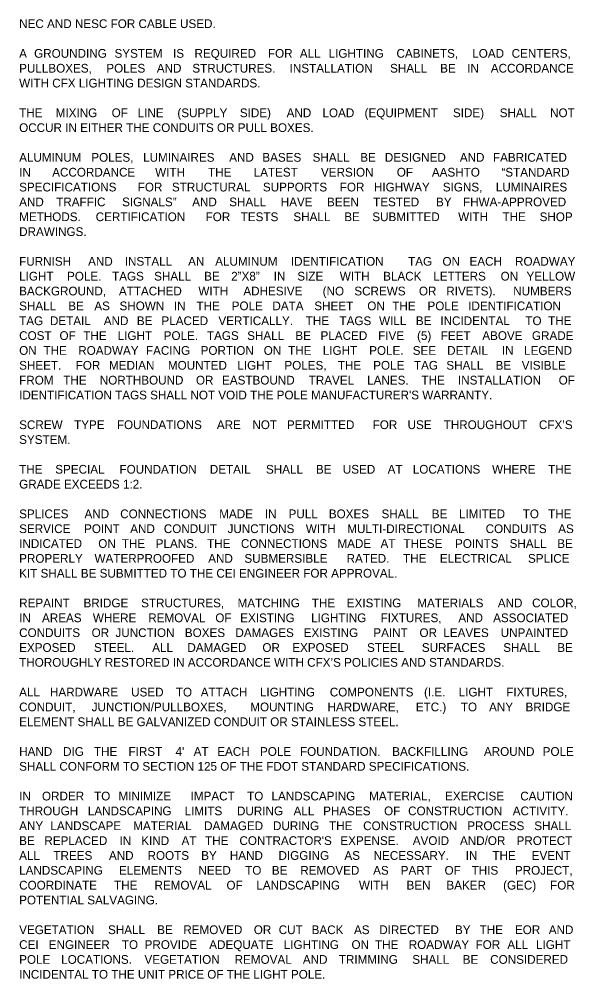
# Model space of a CAD drawing. Extents: x -55 to 2471539, y -90 to 3608906.
# Drawn here: x 568 to 1014, y 8 to 777 of the extents above; entities that cross this region are included whole.
import ezdxf

# ---------------------------------------------------------------- set-up
doc = ezdxf.new("R2010")
doc.units = 0
doc.layers.add('XSCell', color=7, linetype='Continuous')

msp = doc.modelspace()

# ---------------------------------------------------------------- texts
at = {"layer": 'XSCell'}
for s, p in [('NEC AND NESC FOR CABLE USED.', (568.01, 770.14)), ('GROUNDING ', (580.01, 746.34)), ('SYSTEM ', (644.47, 746.34)), ('IS ', (691.38, 746.34)), ('REQUIRED ', (708.58, 746.34)), ('FOR ', (767.49, 746.34)), ('LIGHTING ', (816.15, 746.34)), ('CABINETS, ', (870.55, 746.34)), ('LOAD ', (931.31, 746.34)), ('CENTERS, ', (962.92, 746.34)), ('A ', (568.01, 746.34)), ('ALL ', (793.05, 746.34)), ('PULLBOXES, ', (568.01, 734.44)), ('POLES ', (637.9, 734.44)), ('AND ', (678.37, 734.44)), ('STRUCTURES. ', (706.88, 734.44)), ('INSTALLATION ', (784.88, 734.44)), ('SHALL ', (865.42, 734.44)), ('BE ', (905.55, 734.44)), ('IN ', (927.24, 734.44)), ('ACCORDANCE ', (946.18, 734.44)), ('WITH CFX LIGHTING DESIGN STANDARDS.', (568.01, 722.54)), ('THE ', (568.01, 698.74)), ('MIXING ', (597.31, 698.74)), ('OF ', (642.19, 698.74)), ('LINE ', (663, 698.74)), ('(SUPPLY ', (694.88, 698.74)), ('SIDE) ', (744.95, 698.74)), ('AND ', (782.46, 698.74)), ('LOAD ', (811.22, 698.74)), ('(EQUIPMENT ', (844.96, 698.74)), ('SIDE) ', (915.82, 698.74)), ('SHALL ', (953.33, 698.74)), ('NOT ', (993.71, 698.74)), ('OCCUR IN EITHER THE CONDUITS OR PULL BOXES.', (568.01, 686.84)), ('ALUMINUM ', (568.01, 663.04)), ('POLES, ', (625.83, 663.04)), ('LUMINAIRES ', (667.41, 663.04)), ('AND ', (736.42, 663.04)), ('BASES ', (762.98, 663.04)), ('SHALL ', (803.29, 663.04)), ('BE ', (841.48, 663.04)), ('DESIGNED ', (861.21, 663.04)), ('AND ', (921.34, 663.04)), ('FABRICATED ', (947.9, 663.04)), ('IN ', (568.01, 651.14)), ('ACCORDANCE ', (594.51, 651.14)), ('WITH ', (677.06, 651.14)), ('THE ', (719.43, 651.14)), ('LATEST ', (756.05, 651.14)), ('VERSION ', (810.01, 651.14)), ('OF ', (870.8, 651.14)), ('AASHTO ', (898.93, 651.14)), ('“STANDARD ', (954.69, 651.14)), ('SPECIFICATIONS ', (568.01, 639.24)), ('FOR ', (663.12, 639.24)), ('STRUCTURAL ', (690.51, 639.24)), ('SUPPORTS ', (763.45, 639.24)), ('FOR ', (825.09, 639.24)), ('HIGHWAY ', (852.48, 639.24)), ('SIGNS, ', (907.69, 639.24)), ('LUMINAIRES ', (950.21, 639.24)), ('AND ', (568.01, 627.34)), ('TRAFFIC ', (597.7, 627.34)), ('SIGNALS” ', (650.56, 627.34)), ('AND ', (706.75, 627.34)), ('SHALL ', (736.44, 627.34)), ('HAVE ', (777.76, 627.34)), ('BEEN ', (814.87, 627.34)), ('TESTED ', (851.81, 627.34)), ('BY ', (902.26, 627.34)), ('FHWA-APPROVED ', (923.92, 627.34)), ('METHODS. ', (568.01, 615.44)), ('CERTIFICATION ', (629.39, 615.44)), ('FOR ', (717.5, 615.44)), ('TESTS ', (745.65, 615.44)), ('SHALL ', (787.89, 615.44)), ('BE ', (828.73, 615.44)), ('SUBMITTED ', (851.14, 615.44)), ('WITH ', (920.02, 615.44)), ('THE ', (955.54, 615.44)), ('SHOP ', (985.31, 615.44)), ('DRAWINGS.', (568.01, 603.54)), ('FURNISH ', (568.01, 579.74)), ('AND ', (623.29, 579.74)), ('INSTALL ', (652.69, 579.74)), ('AN ', (703.49, 579.74)), ('ALUMINUM ', (725.21, 579.74)), ('IDENTIFICATION ', (785.87, 579.74)), ('TAG ', (879.86, 579.74)), ('ON ', (907.43, 579.74)), ('EACH ', (929.1, 579.74)), ('ROADWAY ', (965.64, 579.74)), ('LIGHT ', (568.01, 567.84)), ('POLE. ', (606.39, 567.84)), ('TAGS ', (642.51, 567.84)), ('SHALL ', (676.24, 567.84)), ('BE ', (716.34, 567.84)), ('2”X8” ', (738.01, 567.84)), ('IN ', (772.11, 567.84)), ('SIZE ', (791.03, 567.84)), ('WITH ', (825.09, 567.84)), ('BLACK ', (859.87, 567.84)), ('LETTERS ', (900.07, 567.84)), ('ON ', (954.05, 567.84)), ('YELLOW ', (974.8, 567.84)), ('BACKGROUND, ', (568.01, 555.94)), ('ATTACHED ', (647.98, 555.94)), ('WITH ', (711.72, 555.94)), ('ADHESIVE ', (747.77, 555.94)), ('(NO ', (811.36, 555.94)), ('SCREWS ', (836.74, 555.94)), ('OR ', (888.54, 555.94)), ('RIVETS). ', (910.5, 555.94)), ('NUMBERS ', (964.15, 555.94)), ('SHALL ', (568.01, 544.04)), ('BE ', (607.37, 544.04)), ('AS ', (628.28, 544.04)), ('SHOWN ', (648.48, 544.04)), ('IN ', (691.99, 544.04)), ('THE ', (710.16, 544.04)), ('POLE ', (738.44, 544.04)), ('DATA ', (771.06, 544.04)), ('SHEET ', (804.66, 544.04)), ('ON ', (847.15, 544.04)), ('THE ', (867.16, 544.04)), ('POLE ', (895.44, 544.04)), ('IDENTIFICATION ', (928.06, 544.04)), ('TAG ', (568.01, 532.14)), ('DETAIL ', (592.69, 532.14)), ('AND ', (635.86, 532.14)), ('BE ', (662.38, 532.14)), ('PLACED ', (682.08, 532.14)), ('VERTICALLY. ', (727.77, 532.14)), ('THE ', (797.76, 532.14)), ('TAGS ', (824.83, 532.14)), ('WILL ', (856.59, 532.14)), ('BE ', (886.05, 532.14)), ('INCIDENTAL ', (905.75, 532.14)), ('TO ', (973.89, 532.14)), ('THE ', (992.12, 532.14)), ('COST ', (568.01, 520.24)), ('OF ', (600.37, 520.24)), ('THE ', (619.44, 520.24)), ('LIGHT ', (647, 520.24)), ('POLE. ', (683.91, 520.24)), ('TAGS ', (718.57, 520.24)), ('SHALL ', (750.83, 520.24)), ('BE ', (789.47, 520.24)), ('PLACED ', (809.66, 520.24)), ('FIVE ', (855.85, 520.24)), ('(5) ', (887.05, 520.24)), ('FEET ', (906.02, 520.24)), ('ABOVE ', (939.36, 520.24)), ('GRADE ', (979.17, 520.24)), ('ON ', (568.01, 508.34)), ('THE ', (587.57, 508.34)), ('ROADWAY ', (615.39, 508.34)), ('FACING ', (669.69, 508.34)), ('PORTION ', (713.51, 508.34)), ('ON ', (764.09, 508.34)), ('THE ', (783.65, 508.34)), ('LIGHT ', (811.48, 508.34)), ('POLE. ', (848.66, 508.34)), ('SEE ', (883.58, 508.34)), ('DETAIL ', (911.18, 508.34)), ('IN ', (955.12, 508.34)), ('LEGEND ', (972.84, 508.34)), ('SHEET. ', (568.01, 496.44)), ('FOR ', (613.33, 496.44)), ('MEDIAN ', (640.07, 496.44)), ('MOUNTED ', (687.27, 496.44)), ('LIGHT ', (742.99, 496.44)), ('POLES, ', (780.69, 496.44)), ('THE ', (823.52, 496.44)), ('POLE ', (851.88, 496.44)), ('TAG ', (884.57, 496.44)), ('SHALL ', (910.54, 496.44)), ('BE ', (949.98, 496.44)), ('VISIBLE ', (970.96, 496.44)), ('FROM ', (568.01, 484.54)), ('THE ', (603.39, 484.54)), ('NORTHBOUND ', (632.65, 484.54)), ('OR ', (709.75, 484.54)), ('EASTBOUND ', (730.69, 484.54)), ('TRAVEL ', (800.16, 484.54)), ('LANES. ', (847.03, 484.54)), ('THE ', (890.59, 484.54)), ('INSTALLATION ', (919.86, 484.54)), ('OF ', (1000.61, 484.54)), ("IDENTIFICATION TAGS SHALL NOT VOID THE POLE MANUFACTURER'S WARRANTY.", (568.01, 472.64)), ('SCREW ', (568.01, 448.84)), ('TYPE ', (612.05, 448.84)), ('FOUNDATIONS ', (646.38, 448.84)), ('ARE ', (726.54, 448.84)), ('NOT ', (755, 448.84)), ('PERMITTED ', (782.71, 448.84)), ('FOR ', (851.45, 448.84)), ('USE ', (879.44, 448.84)), ('THROUGHOUT ', (908.4, 448.84)), ('CFX’S ', (984.76, 448.84)), ('SYSTEM.', (568.01, 436.94)), ('THE ', (568.01, 413.14)), ('SPECIAL ', (596.95, 413.14)), ('FOUNDATION ', (648.45, 413.14)), ('DETAIL ', (720.86, 413.14)), ('SHALL ', (765.91, 413.14)), ('BE ', (805.93, 413.14)), ('USED ', (827.51, 413.14)), ('AT ', (863.48, 413.14)), ('LOCATIONS ', (883.63, 413.14)), ('WHERE ', (947.18, 413.14)), ('THE ', (992.12, 413.14)), ('GRADE EXCEEDS 1:2.', (568.01, 401.24)), ('SPLICES ', (568.01, 377.44)), ('AND ', (620.4, 377.44)), ('CONNECTIONS ', (649.03, 377.44)), ('MADE ', (728.42, 377.44)), ('IN ', (764.98, 377.44)), ('PULL ', (784.04, 377.44)), ('BOXES ', (816.31, 377.44)), ('SHALL ', (858.59, 377.44)), ('BE ', (898.84, 377.44)), ('LIMITED ', (920.65, 377.44)), ('TO ', (971.78, 377.44)), ('THE ', (992.12, 377.44)), ('SERVICE ', (568.01, 365.54)), ('POINT ', (620.07, 365.54)), ('AND ', (657.06, 365.54)), ('CONDUIT ', (684.01, 365.54)), ('JUNCTIONS ', (735.09, 365.54)), ('WITH ', (797.86, 365.54)), ('MULTI-DIRECTIONAL ', (831.11, 365.54)), ('CONDUITS ', (942.04, 365.54)), ('AS ', (1000.2, 365.54)), ('INDICATED ', (568.01, 353.64)), ('ON ', (631.45, 353.64)), ('THE ', (650.33, 353.64)), ('PLANS. ', (677.5, 353.64)), ('THE ', (718.68, 353.64)), ('CONNECTIONS ', (745.84, 353.64)), ('MADE ', (823.22, 353.64)), ('AT ', (857.76, 353.64)), ('THESE ', (876.13, 353.64)), ('POINTS ', (917.5, 353.64)), ('SHALL ', (961.24, 353.64)), ('BE ', (999.48, 353.64)), ('PROPERLY ', (568.01, 341.74)), ('WATERPROOFED ', (628.45, 341.74)), ('AND ', (719.6, 341.74)), ('SUBMERSIBLE ', (748.61, 341.74)), ('RATED. ', (830.55, 341.74)), ('THE ', (875.77, 341.74)), ('ELECTRICAL ', (905.32, 341.74)), ('SPLICE ', (975.98, 341.74)), ('KIT SHALL BE SUBMITTED TO THE CEI ENGINEER FOR APPROVAL.', (568.01, 329.84)), ('REPAINT ', (568.01, 306.04)), ('BRIDGE ', (619.62, 306.04)), ('STRUCTURES, ', (665.82, 306.04)), ('MATCHING ', (743.13, 306.04)), ('THE ', (802.64, 306.04)), ('EXISTING ', (830.7, 306.04)), ('MATERIALS ', (887.2, 306.04)), ('AND ', (951.78, 306.04)), ('COLOR, ', (979.3, 306.04)), ('IN ', (568.01, 294.14)), ('AREAS ', (586.33, 294.14)), ('WHERE ', (627.11, 294.14)), ('REMOVAL ', (671.54, 294.14)), ('OF ', (725.3, 294.14)), ('EXISTING ', (745.24, 294.14)), ('LIGHTING ', (802.12, 294.14)), ('FIXTURES, ', (857.79, 294.14)), ('AND ', (920.15, 294.14)), ('ASSOCIATED ', (948.05, 294.14)), ('CONDUITS ', (568.01, 282.24)), ('OR ', (626.11, 282.24)), ('JUNCTION ', (645.22, 282.24)), ('BOXES ', (700.86, 282.24)), ('DAMAGES ', (741.4, 282.24)), ('EXISTING ', (796.13, 282.24)), ('PAINT ', (852.01, 282.24)), ('OR ', (888.99, 282.24)), ('LEAVES ', (908.1, 282.24)), ('UNPAINTED ', (954.1, 282.24)), ('EXPOSED ', (568.01, 270.34)), ('STEEL. ', (627.98, 270.34)), ('ALL ', (674.69, 270.34)), ('DAMAGED ', (702.88, 270.34)), ('OR ', (763.04, 270.34)), ('EXPOSED ', (786.96, 270.34)), ('STEEL ', (846.94, 270.34)), ('SURFACES ', (890.89, 270.34)), ('SHALL ', (956.14, 270.34)), ('BE ', (999.48, 270.34)), ('THOROUGHLY RESTORED IN ACCORDANCE WITH CFX’S POLICIES AND STANDARDS. ', (568.01, 258.44)), ('ALL ', (568.01, 234.64)), ('HARDWARE ', (592.75, 234.64)), ('USED ', (657.8, 234.64)), ('TO ', (693.63, 234.64)), ('ATTACH ', (713.61, 234.64)), ('LIGHTING ', (761.04, 234.64)), ('COMPONENTS ', (817.08, 234.64)), ('(I.E. ', (892.66, 234.64)), ('LIGHT ', (920.42, 234.64)), ('FIXTURES, ', (958.58, 234.64)), ('CONDUIT, ', (568.01, 222.74)), ('JUNCTION/PULLBOXES, ', (626.15, 222.74)), ('MOUNTING ', (753.34, 222.74)), ('HARDWARE, ', (815.24, 222.74)), ('ETC.) ', (886.04, 222.74)), ('TO ', (922.13, 222.74)), ('ANY ', (944.79, 222.74)), ('BRIDGE ', (973.98, 222.74)), ('ELEMENT SHALL BE GALVANIZED CONDUIT OR STAINLESS STEEL.', (568.01, 210.84)), ('HAND ', (568.01, 187.04)), ('DIG ', (603.24, 187.04)), ('THE ', (627.99, 187.04)), ('FIRST ', (655.69, 187.04)), ("4' ", (693.4, 187.04)), ('AT ', (707.92, 187.04)), ('EACH ', (726.83, 187.04)), ('POLE ', (761.14, 187.04)), ('FOUNDATION. ', (793.18, 187.04)), ('BACKFILLING ', (867.11, 187.04)), ('AROUND ', (940.66, 187.04)), ('POLE ', (987.78, 187.04)), ('SHALL CONFORM TO SECTION 125 OF THE FDOT STANDARD SPECIFICATIONS.', (568.01, 175.14)), ('IN ', (568.01, 151.34)), ('ORDER ', (586.31, 151.34)), ('TO ', (628.08, 151.34)), ('MINIMIZE ', (647.66, 151.34)), ('IMPACT ', (705.48, 151.34)), ('TO ', (750.79, 151.34)), ('LANDSCAPING ', (770.36, 151.34)), ('MATERIAL, ', (848.58, 151.34)), ('EXERCISE ', (909.49, 151.34)), ('CAUTION ', (969.8, 151.34)), ('THROUGH ', (568.01, 139.44)), ('LANDSCAPING ', (623.09, 139.44)), ('LIMITS ', (700.68, 139.44)), ('DURING ', (742.68, 139.44)), ('ALL ', (788.03, 139.44)), ('PHASES ', (811.75, 139.44)), ('OF ', (860.6, 139.44)), ('CONSTRUCTION ', (879.89, 139.44)), ('ACTIVITY. ', (963.78, 139.44)), ('ANY ', (568.01, 127.54)), ('LANDSCAPE ', (593.07, 127.54)), ('MATERIAL ', (659.49, 127.54)), ('DAMAGED ', (716.29, 127.54)), ('DURING ', (771.54, 127.54)), ('THE ', (816.47, 127.54)), ('CONSTRUCTION ', (843.83, 127.54)), ('PROCESS ', (927.29, 127.54)), ('SHALL ', (981.03, 127.54)), ('BE ', (568.01, 115.64)), ('REPLACED ', (588.23, 115.64)), ('IN ', (648.46, 115.64)), ('KIND ', (665.93, 115.64)), ('AT ', (698.24, 115.64)), ('THE ', (717.04, 115.64)), ("CONTRACTOR'S ", (744.63, 115.64)), ('EXPENSE. ', (825.54, 115.64)), ('AVOID ', (883.61, 115.64)), ('AND/OR ', (921.45, 115.64)), ('PROTECT ', (966.83, 115.64)), ('ALL ', (568.01, 103.74)), ('TREES ', (595.45, 103.74)), ('AND ', (639.99, 103.74)), ('ROOTS ', (670.96, 103.74)), ('BY ', (713.96, 103.74)), ('HAND ', (736.91, 103.74)), ('DIGGING ', (775.95, 103.74)), ('AS ', (828.8, 103.74)), ('NECESSARY. ', (852.22, 103.74)), ('IN ', (926.06, 103.74)), ('THE ', (947.46, 103.74)), ('EVENT ', (978.98, 103.74)), ('LANDSCAPING ', (568.01, 91.84)), ('ELEMENTS ', (648.02, 91.84)), ('NEED ', (711.71, 91.84)), ('TO ', (749.23, 91.84)), ('BE ', (770.6, 91.84)), ('REMOVED ', (793.44, 91.84)), ('AS ', (851.82, 91.84)), ('PART ', (873.94, 91.84)), ('OF ', (909.09, 91.84)), ('THIS ', (930.81, 91.84)), ('PROJECT, ', (965.48, 91.84)), ('COORDINATE ', (568.01, 79.94)), ('THE ', (644.1, 79.94)), ('REMOVAL ', (676.52, 79.94)), ('OF ', (734.26, 79.94)), ('LANDSCAPING ', (758.19, 79.94)), ('WITH ', (840.42, 79.94)), ('BEN ', (878.59, 79.94)), ('BAKER ', (910.58, 79.94)), ('(GEC) ', (956.07, 79.94)), ('FOR ', (993.73, 79.94)), ('POTENTIAL SALVAGING.', (568.01, 68.04)), ('VEGETATION ', (568.01, 44.24)), ('SHALL ', (639.27, 44.24)), ('BE ', (678.67, 44.24)), ('REMOVED ', (699.63, 44.24)), ('OR ', (756.14, 44.24)), ('CUT ', (776.13, 44.24)), ('BACK ', (802.52, 44.24)), ('AS ', (836.47, 44.24)), ('DIRECTED ', (856.71, 44.24)), ('BY ', (917.44, 44.24)), ('THE ', (937.2, 44.24)), ('EOR ', (965.52, 44.24)), ('AND ', (992.65, 44.24)), ('CEI ', (568.01, 32.34)), ('ENGINEER ', (591.75, 32.34)), ('TO ', (650.35, 32.34)), ('PROVIDE ', (668.61, 32.34)), ('ADEQUATE ', (720.42, 32.34)), ('LIGHTING ', (780.17, 32.34)), ('ON ', (834.49, 32.34)), ('THE ', (853.31, 32.34)), ('ROADWAY ', (880.4, 32.34)), ('FOR ', (933.96, 32.34)), ('ALL ', (959.44, 32.34)), ('LIGHT ', (982.46, 32.34)), ('POLE ', (568.01, 20.44)), ('LOCATIONS. ', (601.72, 20.44)), ('VEGETATION ', (668.47, 20.44)), ('REMOVAL ', (740.78, 20.44)), ('AND ', (795.48, 20.44)), ('TRIMMING ', (824.32, 20.44)), ('SHALL ', (883.22, 20.44)), ('BE ', (923.68, 20.44)), ('CONSIDERED ', (945.69, 20.44)), ('INCIDENTAL TO THE UNIT PRICE OF THE LIGHT POLE.', (568.01, 8.54))]:
    msp.add_text(s, height=7, dxfattribs=at).set_placement(p)

doc.saveas('drawing.dxf')
